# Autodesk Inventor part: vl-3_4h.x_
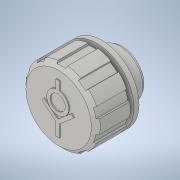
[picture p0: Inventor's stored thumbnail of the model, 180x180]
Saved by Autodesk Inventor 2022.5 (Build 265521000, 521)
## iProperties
Created: 2021-05
Part Number: vl-3_4h.x_
Material: 一般
Document SubType Name: Modeling
Designer: ImaoCorp
Density: 1 g/cm^3
Appearance: 既定
Sending System: SOLIDWORKS 2019-2019304
MC: AMD64
MC_MODEL: Intel64 Family 6 Model 60 Stepping 3, GenuineIntel
OS: Windows_NT
FRU: Parasolid Version 31.0, build 290,  9- 1-2019
FORMAT: text
GUISE: transmit
KEY: vl-3_4h
FILE: vl-3_4h.x_t
DATE: Wed May 19 16:42:58 2021
Author: ImaoCorp
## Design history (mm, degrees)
feature "Base1"
node "ソリッド1"
